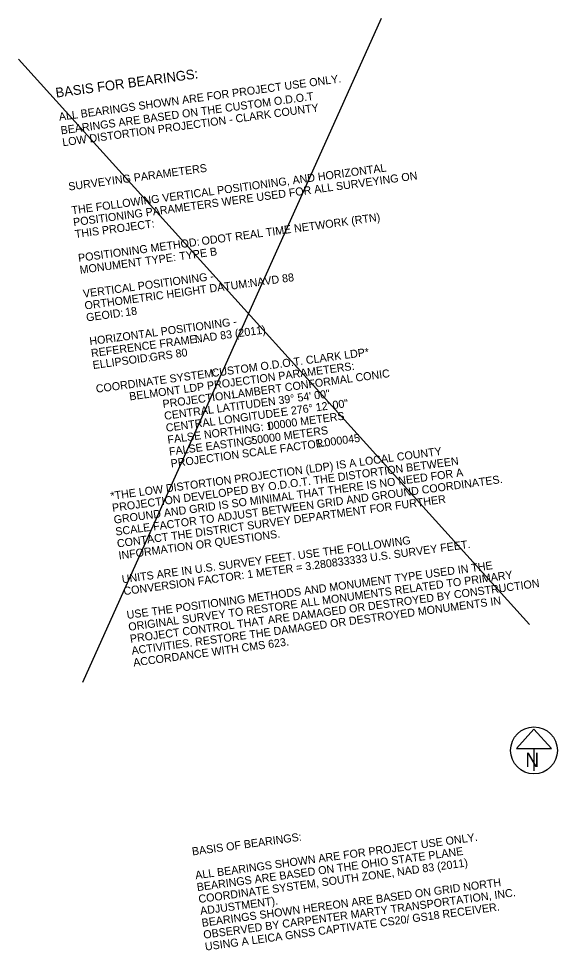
# Model space of a CAD drawing. Extents: x 1569866 to 1574572, y 702112 to 705800.
# Drawn here: x 1573323 to 1574265, y 704170 to 705800 of the extents above; entities that cross this region are included whole.
import ezdxf

# ---------------------------------------------------------------- set-up
doc = ezdxf.new("R2010")
doc.units = 0
for name, color, linetype in [('RW_X_CL_100_Bearings', 7, 'Continuous'), ('RW_X_CL_100_Cardinal_Points', 7, 'Continuous'), ('RW_X_CL_100_Stations', 7, 'Continuous')]:
    doc.layers.add(name, color=color, linetype=linetype)

msp = doc.modelspace()

# ---------------------------------------------------------------- linework, layer by layer
at = {"layer": 'RW_X_CL_100_Bearings'}
msp.add_circle((1574224.5, 704520.1), 41, dxfattribs=at)
at = {"layer": 'RW_X_CL_100_Cardinal_Points'}
for p, q in [((1574224.5, 704557.4), (1574193.7, 704523.3)), ((1574255.2, 704523.3), (1574224.5, 704557.4)), ((1574193.7, 704523.3), (1574255.2, 704523.3)), ((1574224.5, 704523.3), (1574224.5, 704484.6))]:
    msp.add_line(p, q, dxfattribs=at)
msp.add_circle((1574224.5, 704520.1), 41, dxfattribs=at)
at = {"layer": 'RW_X_CL_100_Stations'}
for p, q in [((1573957.1, 705799.6), (1573434.8, 704639)), ((1573322.9, 705728.9), (1574216.7, 704740.3))]:
    msp.add_line(p, q, dxfattribs=at)

# ---------------------------------------------------------------- texts
at = {"layer": 'RW_X_CL_100_Cardinal_Points'}
for s, height, rotation, p in [('BASIS FOR BEARINGS:', 17, 7.7613, (1573388.7, 705661.4)), ('ALL BEARINGS SHOWN ARE FOR PROJECT USE ONLY.', 14, 7.7613, (1573394.2, 705621)), ('BEARINGS ARE BASED ON THE CUSTOM O.D.O.T', 14, 7.7613, (1573397.4, 705597.2)), ('LOW DISTORTION PROJECTION - CLARK COUNTY', 14, 7.7613, (1573400.3, 705576.4)), ('SURVEYING PARAMETERS', 14, 7.7613, (1573410.8, 705499)), ('THE FOLLOWING VERTICAL POSITIONING, AND HORIZONTAL', 14, 7.7613, (1573416.5, 705457.4)), ('POSITIONING PARAMETERS WERE USED FOR ALL SURVEYING ON', 14, 7.7613, (1573419.3, 705436.6)), ('ODOT REAL TIME NETWORK (RTN)', 14, 7.7613, (1573643.9, 705403.6)), ('THIS PROJECT:', 14, 7.7613, (1573422.2, 705415.8)), ('POSITIONING METHOD: ', 14, 7.7613, (1573427.9, 705374.1)), ('MONUMENT TYPE: ', 14, 7.7613, (1573430.7, 705353.3)), ('TYPE B', 14, 7.7613, (1573604.9, 705377.1)), ('VERTICAL POSITIONING -', 14, 7.7613, (1573436.4, 705311.7)), ('NAVD 88', 14, 7.7613, (1573728, 705330.3)), ('ORTHOMETRIC HEIGHT DATUM: ', 14, 7.7613, (1573439.2, 705290.9)), ('GEOID: ', 14, 7.7613, (1573442, 705270.1)), ('18', 14, 7.7613, (1573510.2, 705279.4)), ('HORIZONTAL POSITIONING -', 14, 7.7613, (1573447.7, 705228.5)), ('NAD 83 (2011)', 14, 7.7613, (1573632.1, 705232.4)), ('REFERENCE FRAME: ', 14, 7.7613, (1573450.5, 705207.7)), ('GRS 80', 14, 7.7613, (1573553.1, 705200.5)), ('CUSTOM O.D.O.T. CLARK LDP*', 14, 7.7613, (1573661.5, 705172.9)), ('ELLIPSOID: ', 14, 7.7613, (1573453.4, 705186.9)), ('BELMONT LDP PROJECTION PARAMETERS:', 14, 7.7613, (1573517.4, 705132)), ('COORDINATE SYSTEM: ', 14, 7.7613, (1573459, 705145.3)), ('LAMBERT CONFORMAL CONIC', 14, 7.7613, (1573696.8, 705135.3)), ('PROJECTION: ', 14, 7.7613, (1573575.7, 705118.8)), ('N 39° 54\' 00"', 14, 7.7613, (1573759.8, 705122.7)), ('CENTRAL LATITUDE: ', 14, 7.7613, (1573578.5, 705098)), ('E 276° 12\' 00"', 14, 7.7613, (1573782.6, 705104.6)), ('CENTRAL LONGITUDE: ', 14, 7.7613, (1573581.4, 705077.1)), ('00000 METERS', 14, 7.7613, (1573759.7, 705080.3)), ('FALSE NORTHING: 1', 14, 7.7613, (1573584.2, 705056.3)), ('50000 METERS', 14, 7.7613, (1573730.9, 705055.1)), ('FALSE EASTING: ', 14, 7.7613, (1573587, 705035.5)), ('PROJECTION SCALE FACTOR: ', 14, 7.7613, (1573589.9, 705014.7)), ('1.000045', 14, 7.7613, (1573843.5, 705049.3)), ('*THE LOW DISTORTION PROJECTION (LDP) IS A LOCAL COUNTY', 14, 7.7613, (1573484.6, 704958)), ('PROJECTION DEVELOPED BY O.D.O.T. THE DISTORTION BETWEEN', 14, 7.7613, (1573487.4, 704937.2)), ('GROUND AND GRID IS SO MINIMAL THAT THERE IS NO NEED FOR A', 14, 7.7613, (1573490.2, 704916.4)), ('SCALE FACTOR TO ADJUST BETWEEN GRID AND GROUND COORDINATES.', 14, 7.7613, (1573493.1, 704895.6)), ('CONTACT THE DISTRICT SURVEY DEPARTMENT FOR FURTHER', 14, 7.7613, (1573495.9, 704874.8)), ('INFORMATION OR QUESTIONS.', 14, 7.7613, (1573498.7, 704853.9)), ('UNITS ARE IN U.S. SURVEY FEET. USE THE FOLLOWING', 14, 7.7613, (1573504.4, 704812.3)), ('CONVERSION FACTOR: 1 METER = 3.280833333 U.S. SURVEY FEET.', 14, 7.7613, (1573507.3, 704791.5)), ('USE THE POSITIONING METHODS AND MONUMENT TYPE USED IN THE ', 14, 7.7613, (1573512.9, 704749.9)), ('ORIGINAL SURVEY TO RESTORE ALL MONUMENTS RELATED TO PRIMARY', 14, 7.7613, (1573515.8, 704729.1)), ('PROJECT CONTROL THAT ARE DAMAGED OR DESTROYED BY CONSTRUCTION', 14, 7.7613, (1573518.6, 704708.3)), ('ACTIVITIES. RESTORE THE DAMAGED OR DESTROYED MONUMENTS IN', 14, 7.7613, (1573521.4, 704687.5)), ('ACCORDANCE WITH CMS 623.', 14, 7.7613, (1573524.3, 704666.7)), ('N', 25, 359.9988, (1574209.3, 704490.9)), ('BASIS OF BEARINGS:', 14, 7.7613, (1573627.1, 704336.4)), ('ALL BEARINGS SHOWN ARE FOR PROJECT USE ONLY.', 14, 7.7613, (1573632.8, 704294.8)), ('BEARINGS ARE BASED ON THE OHIO STATE PLANE', 14, 7.7613, (1573635.6, 704274)), ('COORDINATE SYSTEM, SOUTH ZONE, NAD 83 (2011)', 14, 7.7613, (1573638.5, 704253.2)), ('BEARINGS SHOWN HEREON ARE BASED ON GRID NORTH', 14, 7.7613, (1573644.1, 704211.6)), ('OBSERVED BY CARPENTER MARTY TRANSPORTATION, INC.', 14, 7.7613, (1573647, 704190.8)), ('ADJUSTMENT).', 14, 7.7613, (1573641.3, 704232.4)), ('USING A LEICA GNSS CAPTIVATE CS20/ GS18 RECEIVER.', 14, 7.7613, (1573649.8, 704170))]:
    msp.add_text(s, height=height, rotation=rotation, dxfattribs=at).set_placement(p)

doc.saveas('drawing.dxf')
